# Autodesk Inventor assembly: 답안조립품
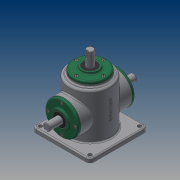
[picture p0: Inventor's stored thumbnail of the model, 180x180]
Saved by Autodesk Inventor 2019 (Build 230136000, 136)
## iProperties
Created: 2019-03
Part Number: 답안조립품
Material: 일반
Document SubType Name: Assembly
Designer: PC312-20
Author: PC312-20
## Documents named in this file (16)
- C:\Users\PC312-20\Desktop\490314V1002\답안조립품.iam
- C:\Users\PC312-20\Desktop\490314V1002\본체.ipt
- C:\Users\PC312-20\Desktop\490314V1002\커버.ipt
- C:\Users\PC312-20\Desktop\490314V1002\볼트 M4.ipt
- 볼트 M4.ipt
- C:\Users\PC312-20\Desktop\490314V1002\베어링 6203.ipt
- C:\Users\PC312-20\Desktop\490314V1002\메인 축.ipt
- 메인 축.ipt
- C:\Users\PC312-20\Desktop\490314V1002\서브 축.ipt
- 서브 축.ipt
- C:\Users\PC312-20\Desktop\490314V1002\키 5x5.ipt
- C:\Users\PC312-20\Desktop\490314V1002\키 4x4.ipt
- C:\Users\PC312-20\Desktop\490314V1002\오일 실.ipt
- 오일 실.ipt
- C:\Users\PC312-20\Desktop\490314V1002\메인 베벨기어.ipt
- C:\Users\PC312-20\Desktop\490314V1002\서브 베벨기어.ipt
